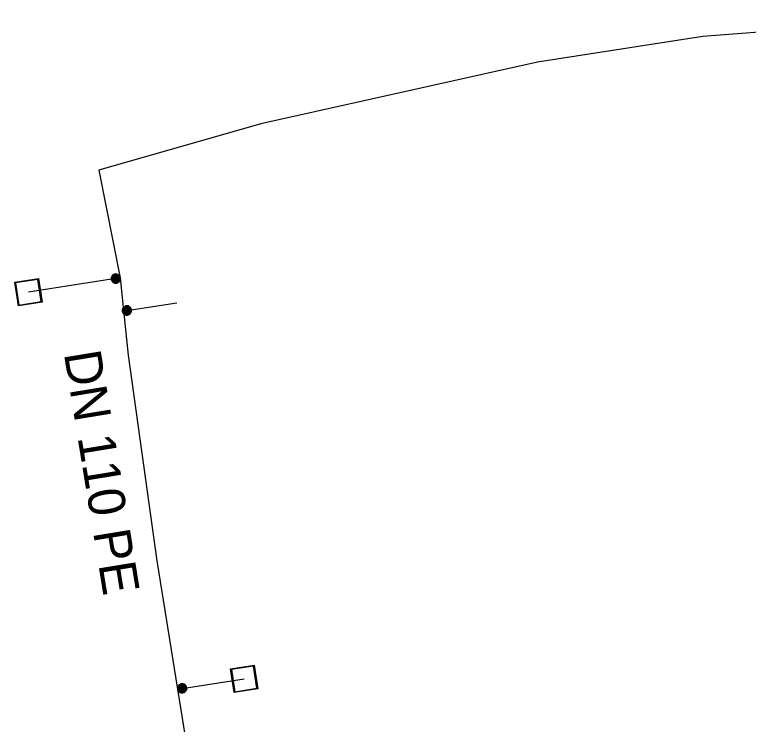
# Model space of a CAD drawing. Extents: x -832382 to -831581, y -1074670 to -1074251.
# Drawn here: x -831957.96 to -831918.15, y -1074447.07 to -1074408.59 of the extents above; entities that cross this region are included whole.
import ezdxf

# ---------------------------------------------------------------- set-up
doc = ezdxf.new("R2010")
doc.units = 0
for name, color, linetype in [('Přípojka vodovodu', 7, 'Continuous'), ('Přípojkový uzávěr', 7, 'Continuous'), ('Roz-řad', 7, 'Continuous'), ('Roz-řad-popis základní', 7, 'Continuous'), ('Šachta vodovodní', 7, 'Continuous')]:
    doc.layers.add(name, color=color, linetype=linetype)

msp = doc.modelspace()

# ---------------------------------------------------------------- linework, layer by layer
at = {"layer": 'Přípojka vodovodu'}
for points in [[(-831952.245, -1074422.863), (-831952.48, -1074422.9), (-831957.22, -1074423.64)], [(-831952.065, -1074424.626), (-831951.874, -1074424.626), (-831949.165, -1074424.217)], [(-831949.124, -1074445.161), (-831948.872, -1074445.122), (-831945.511, -1074444.606)]]:
    msp.add_lwpolyline(points, dxfattribs=at)
at = {"layer": 'Přípojkový uzávěr'}
for points in [[(-831952.48, -1074422.65), (-831952.417, -1074422.65), (-831952.357, -1074422.682), (-831952.298, -1074422.714), (-831952.264, -1074422.775), (-831952.23, -1074422.835), (-831952.23, -1074422.9), (-831952.23, -1074422.965), (-831952.263, -1074423.025), (-831952.296, -1074423.084), (-831952.355, -1074423.117), (-831952.415, -1074423.15), (-831952.48, -1074423.15), (-831952.545, -1074423.15), (-831952.605, -1074423.117), (-831952.664, -1074423.084), (-831952.697, -1074423.025), (-831952.73, -1074422.965), (-831952.73, -1074422.9), (-831952.73, -1074422.835), (-831952.696, -1074422.775), (-831952.663, -1074422.714), (-831952.603, -1074422.682), (-831952.543, -1074422.65), (-831952.48, -1074422.65)], [(-831952.48, -1074422.673), (-831952.537, -1074422.673), (-831952.592, -1074422.703), (-831952.646, -1074422.732), (-831952.676, -1074422.786), (-831952.707, -1074422.841), (-831952.707, -1074422.9), (-831952.707, -1074422.959), (-831952.677, -1074423.013), (-831952.647, -1074423.067), (-831952.593, -1074423.097), (-831952.539, -1074423.127), (-831952.48, -1074423.127), (-831952.421, -1074423.127), (-831952.367, -1074423.097), (-831952.313, -1074423.067), (-831952.283, -1074423.013), (-831952.253, -1074422.959), (-831952.253, -1074422.9), (-831952.253, -1074422.841), (-831952.284, -1074422.786), (-831952.315, -1074422.732), (-831952.369, -1074422.703), (-831952.423, -1074422.673), (-831952.48, -1074422.673)], [(-831952.48, -1074422.691), (-831952.427, -1074422.691), (-831952.377, -1074422.718), (-831952.327, -1074422.744), (-831952.299, -1074422.795), (-831952.271, -1074422.845), (-831952.271, -1074422.9), (-831952.271, -1074422.955), (-831952.298, -1074423.004), (-831952.325, -1074423.054), (-831952.376, -1074423.082), (-831952.426, -1074423.109), (-831952.48, -1074423.109), (-831952.534, -1074423.109), (-831952.584, -1074423.082), (-831952.635, -1074423.054), (-831952.662, -1074423.004), (-831952.689, -1074422.955), (-831952.689, -1074422.9), (-831952.689, -1074422.845), (-831952.661, -1074422.795), (-831952.633, -1074422.744), (-831952.583, -1074422.718), (-831952.533, -1074422.691), (-831952.48, -1074422.691)], [(-831952.48, -1074422.713), (-831952.559, -1074422.713), (-831952.613, -1074422.767), (-831952.668, -1074422.822), (-831952.668, -1074422.9), (-831952.668, -1074422.978), (-831952.613, -1074423.033), (-831952.558, -1074423.088), (-831952.48, -1074423.088), (-831952.402, -1074423.088), (-831952.347, -1074423.033), (-831952.293, -1074422.978), (-831952.293, -1074422.9), (-831952.293, -1074422.822), (-831952.347, -1074422.767), (-831952.402, -1074422.713), (-831952.48, -1074422.713)], [(-831952.48, -1074422.735), (-831952.412, -1074422.735), (-831952.364, -1074422.783), (-831952.316, -1074422.831), (-831952.316, -1074422.9), (-831952.316, -1074422.968), (-831952.364, -1074423.016), (-831952.412, -1074423.064), (-831952.48, -1074423.064), (-831952.549, -1074423.064), (-831952.597, -1074423.016), (-831952.645, -1074422.968), (-831952.645, -1074422.9), (-831952.645, -1074422.831), (-831952.597, -1074422.783), (-831952.549, -1074422.735), (-831952.48, -1074422.735)], [(-831952.48, -1074422.755), (-831952.541, -1074422.755), (-831952.583, -1074422.797), (-831952.625, -1074422.84), (-831952.625, -1074422.9), (-831952.625, -1074422.959), (-831952.583, -1074423.002), (-831952.541, -1074423.044), (-831952.48, -1074423.044), (-831952.421, -1074423.044), (-831952.378, -1074423.002), (-831952.336, -1074422.959), (-831952.336, -1074422.9), (-831952.336, -1074422.84), (-831952.378, -1074422.797), (-831952.42, -1074422.755), (-831952.48, -1074422.755)], [(-831952.48, -1074422.775), (-831952.428, -1074422.775), (-831952.391, -1074422.812), (-831952.355, -1074422.848), (-831952.355, -1074422.9), (-831952.355, -1074422.952), (-831952.392, -1074422.989), (-831952.428, -1074423.025), (-831952.48, -1074423.025), (-831952.532, -1074423.025), (-831952.568, -1074422.989), (-831952.605, -1074422.952), (-831952.605, -1074422.9), (-831952.605, -1074422.848), (-831952.569, -1074422.812), (-831952.532, -1074422.775), (-831952.48, -1074422.775)], [(-831952.48, -1074422.798), (-831952.522, -1074422.798), (-831952.552, -1074422.828), (-831952.582, -1074422.858), (-831952.582, -1074422.9), (-831952.582, -1074422.942), (-831952.552, -1074422.972), (-831952.522, -1074423.001), (-831952.48, -1074423.001), (-831952.438, -1074423.001), (-831952.408, -1074422.972), (-831952.379, -1074422.942), (-831952.379, -1074422.9), (-831952.379, -1074422.858), (-831952.408, -1074422.828), (-831952.438, -1074422.798), (-831952.48, -1074422.798)], [(-831952.48, -1074422.816), (-831952.445, -1074422.816), (-831952.421, -1074422.84), (-831952.396, -1074422.865), (-831952.396, -1074422.9), (-831952.396, -1074422.935), (-831952.421, -1074422.959), (-831952.445, -1074422.984), (-831952.48, -1074422.984), (-831952.515, -1074422.984), (-831952.54, -1074422.959), (-831952.564, -1074422.935), (-831952.564, -1074422.9), (-831952.564, -1074422.865), (-831952.54, -1074422.84), (-831952.515, -1074422.816), (-831952.48, -1074422.816)], [(-831952.48, -1074422.838), (-831952.506, -1074422.838), (-831952.524, -1074422.856), (-831952.543, -1074422.874), (-831952.543, -1074422.9), (-831952.543, -1074422.926), (-831952.524, -1074422.944), (-831952.506, -1074422.963), (-831952.48, -1074422.963), (-831952.454, -1074422.963), (-831952.436, -1074422.944), (-831952.418, -1074422.926), (-831952.418, -1074422.9), (-831952.418, -1074422.874), (-831952.436, -1074422.856), (-831952.454, -1074422.838), (-831952.48, -1074422.838)], [(-831952.48, -1074422.861), (-831952.464, -1074422.861), (-831952.452, -1074422.872), (-831952.441, -1074422.883), (-831952.441, -1074422.9), (-831952.441, -1074422.916), (-831952.452, -1074422.928), (-831952.464, -1074422.939), (-831952.48, -1074422.939), (-831952.496, -1074422.939), (-831952.508, -1074422.928), (-831952.519, -1074422.916), (-831952.519, -1074422.9), (-831952.519, -1074422.883), (-831952.508, -1074422.872), (-831952.496, -1074422.861), (-831952.48, -1074422.861)], [(-831952.48, -1074422.877), (-831952.49, -1074422.877), (-831952.497, -1074422.883), (-831952.504, -1074422.89), (-831952.504, -1074422.9), (-831952.504, -1074422.91), (-831952.497, -1074422.917), (-831952.49, -1074422.923), (-831952.48, -1074422.923), (-831952.47, -1074422.923), (-831952.464, -1074422.917), (-831952.457, -1074422.91), (-831952.457, -1074422.9), (-831952.457, -1074422.89), (-831952.464, -1074422.883), (-831952.47, -1074422.877), (-831952.48, -1074422.877)], [(-831951.874, -1074424.376), (-831951.811, -1074424.376), (-831951.751, -1074424.408), (-831951.692, -1074424.441), (-831951.658, -1074424.501), (-831951.624, -1074424.561), (-831951.624, -1074424.626), (-831951.624, -1074424.691), (-831951.657, -1074424.751), (-831951.69, -1074424.81), (-831951.749, -1074424.843), (-831951.809, -1074424.876), (-831951.874, -1074424.876), (-831951.939, -1074424.876), (-831951.998, -1074424.843), (-831952.058, -1074424.81), (-831952.091, -1074424.751), (-831952.124, -1074424.691), (-831952.124, -1074424.626), (-831952.124, -1074424.561), (-831952.09, -1074424.501), (-831952.057, -1074424.441), (-831951.997, -1074424.408), (-831951.937, -1074424.376), (-831951.874, -1074424.376)], [(-831951.874, -1074424.4), (-831951.931, -1074424.4), (-831951.986, -1074424.429), (-831952.04, -1074424.458), (-831952.07, -1074424.512), (-831952.101, -1074424.567), (-831952.101, -1074424.626), (-831952.101, -1074424.685), (-831952.071, -1074424.739), (-831952.041, -1074424.793), (-831951.987, -1074424.823), (-831951.933, -1074424.853), (-831951.874, -1074424.853), (-831951.815, -1074424.853), (-831951.761, -1074424.823), (-831951.707, -1074424.793), (-831951.677, -1074424.739), (-831951.647, -1074424.685), (-831951.647, -1074424.626), (-831951.647, -1074424.567), (-831951.678, -1074424.512), (-831951.709, -1074424.458), (-831951.763, -1074424.429), (-831951.817, -1074424.4), (-831951.874, -1074424.4)], [(-831951.874, -1074424.417), (-831951.821, -1074424.417), (-831951.771, -1074424.444), (-831951.721, -1074424.471), (-831951.693, -1074424.521), (-831951.665, -1074424.571), (-831951.665, -1074424.626), (-831951.665, -1074424.681), (-831951.692, -1074424.731), (-831951.719, -1074424.78), (-831951.769, -1074424.808), (-831951.82, -1074424.836), (-831951.874, -1074424.836), (-831951.928, -1074424.836), (-831951.978, -1074424.808), (-831952.029, -1074424.78), (-831952.056, -1074424.731), (-831952.083, -1074424.681), (-831952.083, -1074424.626), (-831952.083, -1074424.571), (-831952.055, -1074424.521), (-831952.027, -1074424.471), (-831951.977, -1074424.444), (-831951.927, -1074424.417), (-831951.874, -1074424.417)], [(-831951.874, -1074424.439), (-831951.953, -1074424.439), (-831952.007, -1074424.494), (-831952.061, -1074424.548), (-831952.061, -1074424.626), (-831952.061, -1074424.704), (-831952.007, -1074424.759), (-831951.952, -1074424.814), (-831951.874, -1074424.814), (-831951.796, -1074424.814), (-831951.741, -1074424.759), (-831951.686, -1074424.704), (-831951.686, -1074424.626), (-831951.686, -1074424.548), (-831951.741, -1074424.494), (-831951.796, -1074424.439), (-831951.874, -1074424.439)], [(-831951.874, -1074424.462), (-831951.806, -1074424.462), (-831951.758, -1074424.51), (-831951.71, -1074424.558), (-831951.71, -1074424.626), (-831951.71, -1074424.694), (-831951.758, -1074424.742), (-831951.806, -1074424.79), (-831951.874, -1074424.79), (-831951.943, -1074424.79), (-831951.991, -1074424.742), (-831952.039, -1074424.694), (-831952.039, -1074424.626), (-831952.039, -1074424.558), (-831951.991, -1074424.51), (-831951.943, -1074424.462), (-831951.874, -1074424.462)], [(-831951.874, -1074424.481), (-831951.935, -1074424.481), (-831951.977, -1074424.524), (-831952.019, -1074424.566), (-831952.019, -1074424.626), (-831952.019, -1074424.685), (-831951.977, -1074424.728), (-831951.935, -1074424.77), (-831951.874, -1074424.77), (-831951.815, -1074424.77), (-831951.772, -1074424.728), (-831951.73, -1074424.685), (-831951.73, -1074424.626), (-831951.73, -1074424.566), (-831951.772, -1074424.524), (-831951.814, -1074424.481), (-831951.874, -1074424.481)], [(-831951.874, -1074424.501), (-831951.822, -1074424.501), (-831951.785, -1074424.538), (-831951.749, -1074424.574), (-831951.749, -1074424.626), (-831951.749, -1074424.678), (-831951.786, -1074424.715), (-831951.822, -1074424.751), (-831951.874, -1074424.751), (-831951.926, -1074424.751), (-831951.962, -1074424.715), (-831951.999, -1074424.678), (-831951.999, -1074424.626), (-831951.999, -1074424.574), (-831951.963, -1074424.538), (-831951.926, -1074424.501), (-831951.874, -1074424.501)], [(-831951.874, -1074424.524), (-831951.916, -1074424.524), (-831951.946, -1074424.554), (-831951.976, -1074424.584), (-831951.976, -1074424.626), (-831951.976, -1074424.668), (-831951.946, -1074424.698), (-831951.916, -1074424.727), (-831951.874, -1074424.727), (-831951.832, -1074424.727), (-831951.802, -1074424.698), (-831951.773, -1074424.668), (-831951.773, -1074424.626), (-831951.773, -1074424.584), (-831951.802, -1074424.554), (-831951.832, -1074424.524), (-831951.874, -1074424.524)], [(-831951.874, -1074424.542), (-831951.839, -1074424.542), (-831951.815, -1074424.566), (-831951.79, -1074424.591), (-831951.79, -1074424.626), (-831951.79, -1074424.661), (-831951.815, -1074424.686), (-831951.839, -1074424.71), (-831951.874, -1074424.71), (-831951.909, -1074424.71), (-831951.934, -1074424.686), (-831951.958, -1074424.661), (-831951.958, -1074424.626), (-831951.958, -1074424.591), (-831951.934, -1074424.566), (-831951.909, -1074424.542), (-831951.874, -1074424.542)], [(-831951.874, -1074424.564), (-831951.9, -1074424.564), (-831951.918, -1074424.582), (-831951.936, -1074424.6), (-831951.936, -1074424.626), (-831951.936, -1074424.652), (-831951.918, -1074424.67), (-831951.9, -1074424.689), (-831951.874, -1074424.689), (-831951.848, -1074424.689), (-831951.83, -1074424.67), (-831951.811, -1074424.652), (-831951.811, -1074424.626), (-831951.811, -1074424.6), (-831951.83, -1074424.582), (-831951.848, -1074424.564), (-831951.874, -1074424.564)], [(-831951.874, -1074424.587), (-831951.858, -1074424.587), (-831951.846, -1074424.598), (-831951.835, -1074424.61), (-831951.835, -1074424.626), (-831951.835, -1074424.642), (-831951.846, -1074424.654), (-831951.858, -1074424.665), (-831951.874, -1074424.665), (-831951.89, -1074424.665), (-831951.902, -1074424.654), (-831951.913, -1074424.642), (-831951.913, -1074424.626), (-831951.913, -1074424.61), (-831951.902, -1074424.598), (-831951.89, -1074424.587), (-831951.874, -1074424.587)], [(-831951.874, -1074424.603), (-831951.884, -1074424.603), (-831951.891, -1074424.609), (-831951.898, -1074424.616), (-831951.898, -1074424.626), (-831951.898, -1074424.636), (-831951.891, -1074424.643), (-831951.884, -1074424.65), (-831951.874, -1074424.65), (-831951.864, -1074424.65), (-831951.857, -1074424.643), (-831951.851, -1074424.636), (-831951.851, -1074424.626), (-831951.851, -1074424.616), (-831951.857, -1074424.609), (-831951.864, -1074424.603), (-831951.874, -1074424.603)], [(-831948.834, -1074445.37), (-831948.896, -1074445.379), (-831948.96, -1074445.356), (-831949.024, -1074445.334), (-831949.067, -1074445.279), (-831949.11, -1074445.225), (-831949.12, -1074445.16), (-831949.129, -1074445.096), (-831949.106, -1074445.032), (-831949.082, -1074444.969), (-831949.028, -1074444.927), (-831948.975, -1074444.885), (-831948.91, -1074444.875), (-831948.846, -1074444.866), (-831948.782, -1074444.889), (-831948.718, -1074444.913), (-831948.677, -1074444.966), (-831948.635, -1074445.02), (-831948.625, -1074445.084), (-831948.615, -1074445.149), (-831948.639, -1074445.214), (-831948.663, -1074445.278), (-831948.718, -1074445.319), (-831948.772, -1074445.36), (-831948.834, -1074445.37)], [(-831948.838, -1074445.346), (-831948.781, -1074445.338), (-831948.732, -1074445.301), (-831948.683, -1074445.264), (-831948.661, -1074445.205), (-831948.639, -1074445.146), (-831948.649, -1074445.088), (-831948.657, -1074445.03), (-831948.695, -1074444.981), (-831948.733, -1074444.932), (-831948.791, -1074444.911), (-831948.849, -1074444.89), (-831948.907, -1074444.899), (-831948.965, -1074444.907), (-831949.014, -1074444.945), (-831949.063, -1074444.983), (-831949.084, -1074445.041), (-831949.105, -1074445.099), (-831949.096, -1074445.157), (-831949.087, -1074445.215), (-831949.049, -1074445.265), (-831949.01, -1074445.314), (-831948.952, -1074445.334), (-831948.894, -1074445.355), (-831948.838, -1074445.346)], [(-831948.84, -1074445.329), (-831948.893, -1074445.338), (-831948.946, -1074445.318), (-831949, -1074445.299), (-831949.035, -1074445.254), (-831949.071, -1074445.208), (-831949.079, -1074445.154), (-831949.088, -1074445.1), (-831949.068, -1074445.047), (-831949.049, -1074444.993), (-831949.003, -1074444.959), (-831948.958, -1074444.924), (-831948.904, -1074444.915), (-831948.85, -1074444.907), (-831948.797, -1074444.927), (-831948.743, -1074444.947), (-831948.708, -1074444.992), (-831948.674, -1074445.037), (-831948.665, -1074445.09), (-831948.657, -1074445.145), (-831948.677, -1074445.199), (-831948.697, -1074445.253), (-831948.743, -1074445.287), (-831948.788, -1074445.321), (-831948.84, -1074445.329)], [(-831948.843, -1074445.308), (-831948.766, -1074445.296), (-831948.721, -1074445.233), (-831948.675, -1074445.171), (-831948.687, -1074445.094), (-831948.699, -1074445.017), (-831948.762, -1074444.971), (-831948.824, -1074444.925), (-831948.9, -1074444.937), (-831948.978, -1074444.949), (-831949.024, -1074445.011), (-831949.07, -1074445.074), (-831949.058, -1074445.151), (-831949.046, -1074445.228), (-831948.984, -1074445.274), (-831948.921, -1074445.32), (-831948.843, -1074445.308)], [(-831948.847, -1074445.285), (-831948.915, -1074445.295), (-831948.969, -1074445.255), (-831949.024, -1074445.215), (-831949.034, -1074445.148), (-831949.044, -1074445.081), (-831949.004, -1074445.026), (-831948.964, -1074444.971), (-831948.897, -1074444.961), (-831948.829, -1074444.95), (-831948.775, -1074444.991), (-831948.72, -1074445.031), (-831948.71, -1074445.098), (-831948.699, -1074445.165), (-831948.739, -1074445.22), (-831948.779, -1074445.275), (-831948.847, -1074445.285)], [(-831948.85, -1074445.266), (-831948.791, -1074445.256), (-831948.755, -1074445.208), (-831948.72, -1074445.16), (-831948.729, -1074445.101), (-831948.738, -1074445.042), (-831948.786, -1074445.007), (-831948.834, -1074444.971), (-831948.894, -1074444.98), (-831948.953, -1074444.989), (-831948.988, -1074445.038), (-831949.024, -1074445.086), (-831949.014, -1074445.145), (-831949.005, -1074445.204), (-831948.957, -1074445.239), (-831948.91, -1074445.275), (-831948.85, -1074445.266)], [(-831948.853, -1074445.246), (-831948.905, -1074445.254), (-831948.947, -1074445.223), (-831948.988, -1074445.193), (-831948.996, -1074445.141), (-831949.004, -1074445.09), (-831948.973, -1074445.048), (-831948.943, -1074445.007), (-831948.891, -1074444.999), (-831948.84, -1074444.991), (-831948.798, -1074445.022), (-831948.757, -1074445.052), (-831948.749, -1074445.103), (-831948.741, -1074445.155), (-831948.771, -1074445.196), (-831948.802, -1074445.238), (-831948.853, -1074445.246)], [(-831948.857, -1074445.223), (-831948.815, -1074445.217), (-831948.79, -1074445.183), (-831948.765, -1074445.149), (-831948.772, -1074445.107), (-831948.778, -1074445.066), (-831948.812, -1074445.041), (-831948.846, -1074445.016), (-831948.888, -1074445.022), (-831948.929, -1074445.029), (-831948.954, -1074445.063), (-831948.979, -1074445.096), (-831948.973, -1074445.138), (-831948.966, -1074445.18), (-831948.932, -1074445.205), (-831948.898, -1074445.229), (-831948.857, -1074445.223)], [(-831948.859, -1074445.206), (-831948.894, -1074445.211), (-831948.922, -1074445.191), (-831948.95, -1074445.17), (-831948.955, -1074445.135), (-831948.961, -1074445.101), (-831948.94, -1074445.073), (-831948.919, -1074445.045), (-831948.885, -1074445.039), (-831948.85, -1074445.034), (-831948.822, -1074445.055), (-831948.794, -1074445.075), (-831948.789, -1074445.11), (-831948.784, -1074445.145), (-831948.804, -1074445.173), (-831948.825, -1074445.201), (-831948.859, -1074445.206)], [(-831948.863, -1074445.184), (-831948.837, -1074445.18), (-831948.822, -1074445.159), (-831948.807, -1074445.139), (-831948.811, -1074445.113), (-831948.815, -1074445.087), (-831948.835, -1074445.072), (-831948.856, -1074445.057), (-831948.882, -1074445.061), (-831948.907, -1074445.065), (-831948.923, -1074445.086), (-831948.938, -1074445.106), (-831948.934, -1074445.132), (-831948.93, -1074445.158), (-831948.909, -1074445.173), (-831948.889, -1074445.188), (-831948.863, -1074445.184)], [(-831948.866, -1074445.161), (-831948.883, -1074445.164), (-831948.895, -1074445.154), (-831948.908, -1074445.145), (-831948.911, -1074445.128), (-831948.913, -1074445.112), (-831948.904, -1074445.099), (-831948.895, -1074445.086), (-831948.878, -1074445.084), (-831948.862, -1074445.081), (-831948.849, -1074445.091), (-831948.836, -1074445.101), (-831948.834, -1074445.117), (-831948.831, -1074445.133), (-831948.841, -1074445.146), (-831948.85, -1074445.159), (-831948.866, -1074445.161)], [(-831948.869, -1074445.146), (-831948.859, -1074445.144), (-831948.853, -1074445.136), (-831948.847, -1074445.129), (-831948.849, -1074445.119), (-831948.85, -1074445.109), (-831948.858, -1074445.104), (-831948.866, -1074445.098), (-831948.876, -1074445.099), (-831948.886, -1074445.101), (-831948.891, -1074445.109), (-831948.897, -1074445.116), (-831948.895, -1074445.126), (-831948.894, -1074445.136), (-831948.886, -1074445.142), (-831948.878, -1074445.147), (-831948.869, -1074445.146)]]:
    msp.add_open_spline(points, degree=3, dxfattribs=at)
at = {"layer": 'Roz-řad'}
msp.add_lwpolyline([(-831886.44, -1074408.64), (-831905.34, -1074408.59), (-831920.63, -1074409.77), (-831929.6, -1074411.16), (-831944.61, -1074414.5), (-831953.4, -1074417.02), (-831952.245, -1074422.863), (-831952.065, -1074424.626), (-831951.81, -1074427.06), (-831950.24, -1074438.21), (-831949.124, -1074445.161), (-831946.578, -1074461.011), (-831946.13, -1074461.88)], dxfattribs=at)
at = {"layer": 'Šachta vodovodní'}
for points in [[(-831956.678, -1074422.898), (-831956.478, -1074424.182), (-831957.762, -1074424.382), (-831957.962, -1074423.098), (-831956.678, -1074422.898)], [(-831957.916, -1074423.132), (-831957.728, -1074424.336), (-831956.524, -1074424.148), (-831956.712, -1074422.944), (-831957.916, -1074423.132)], [(-831944.967, -1074443.865), (-831944.77, -1074445.15), (-831946.055, -1074445.347), (-831946.252, -1074444.062), (-831944.967, -1074443.865)], [(-831946.206, -1074444.096), (-831946.021, -1074445.301), (-831944.816, -1074445.116), (-831945.001, -1074443.911), (-831946.206, -1074444.096)]]:
    msp.add_lwpolyline(points, dxfattribs=at)

# ---------------------------------------------------------------- texts
at = {"layer": 'Roz-řad-popis základní'}
msp.add_text('DN 110 PE', height=2, rotation=279.3023, dxfattribs=at).set_placement((-831955.298, -1074426.953))

doc.saveas('drawing.dxf')
